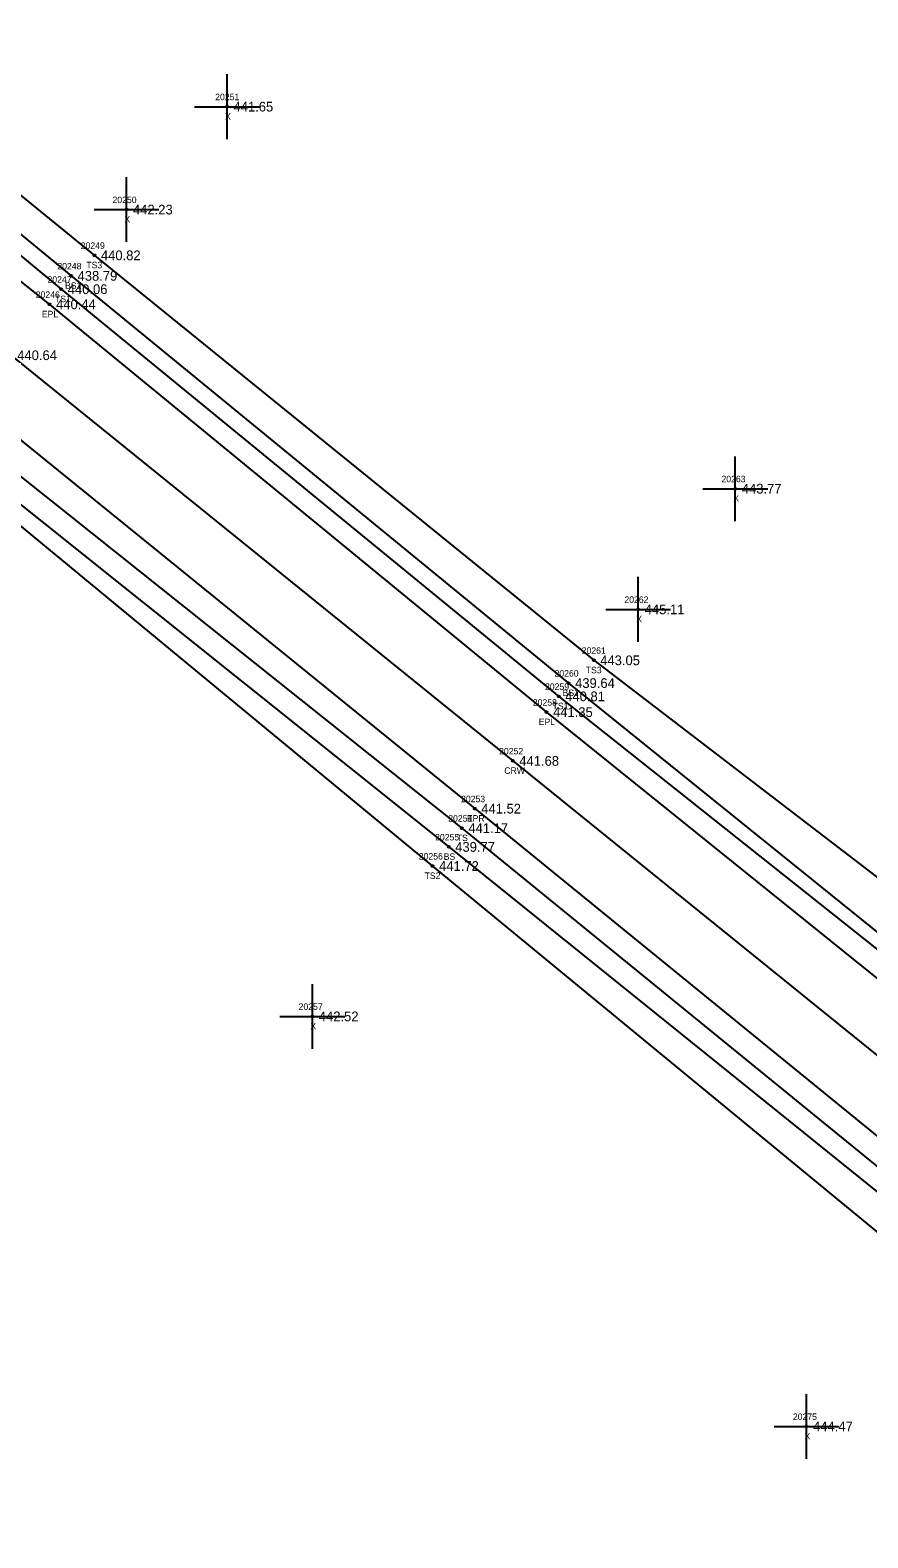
# Model space of a CAD drawing. Extents: x 1613836 to 1615109, y 777151 to 778248.
# Drawn here: x 1614680.1 to 1614809.5, y 777339.3 to 777572.2 of the extents above; entities that cross this region are included whole.
import ezdxf

# ---------------------------------------------------------------- set-up
doc = ezdxf.new("R2010")
doc.units = 0
for name, color, linetype in [('RD_DTM_BkLn1', 7, 'Continuous'), ('RD_DTM_BkLn2', 7, 'Continuous'), ('RD_DTM_BkLn_txCode', 7, 'Continuous'), ('RD_EX_Misc', 7, 'Continuous'), ('RD_EX_Misc_txCode', 7, 'Continuous'), ('RD_EX_Road', 7, 'Continuous'), ('RD_EX_Road_txCode', 7, 'Continuous'), ('RD_EX_TX_Misc_ELEV', 7, 'Continuous'), ('RD_EX_TX_Road_ELEV', 7, 'Continuous'), ('RD_HC_Survey_ELEV', 7, 'Continuous'), ('RD_HC_Survey_txCode', 7, 'Continuous'), ('RD_SMD_Locator', 7, 'Continuous')]:
    doc.layers.add(name, color=color, linetype=linetype)

msp = doc.modelspace()

# ---------------------------------------------------------------- linework, layer by layer
at = {"layer": 'RD_DTM_BkLn1'}
msp.add_lwpolyline([(1614479.01, 777681.63), (1614521.59, 777647.42), (1614599.56, 777584.67), (1614677.14, 777521.99), (1614754.7, 777459.32), (1614832.45, 777396.45), (1614909.52, 777332.99), (1614951.1, 777299.39), (1614987.2, 777270.31), (1615065.15, 777207.54)], dxfattribs=at)
at = {"layer": 'RD_DTM_BkLn2'}
for points in [[(1614480.98, 777699.79), (1614497.59, 777703), (1614522.19, 777696.07), (1614543.87, 777680.98), (1614547.65, 777678.09), (1614587.23, 777635.96), (1614610.74, 777599.44), (1614633.11, 777578.17), (1614686.46, 777534.25), (1614763.32, 777471.34), (1614841.29, 777408.4), (1614909.19, 777352.07)], [(1614487.8, 777694.98), (1614468.11, 777671.48), (1614470.95, 777667.94), (1614510.68, 777634.64), (1614563.11, 777597.11), (1614590.8, 777573.1), (1614668.37, 777511.43), (1614746.83, 777448.93), (1614824, 777386.05), (1614902.11, 777323.38), (1614943.6, 777288.77), (1614978.33, 777258.85), (1615057.35, 777197.32)], [(1614487.8, 777694.98), (1614492.09, 777693.24), (1614539.12, 777670.15), (1614581.25, 777629.02), (1614608.07, 777595.47), (1614631.79, 777576.16), (1614684.94, 777532.19), (1614761.79, 777469.29), (1614840.42, 777406.78), (1614908.46, 777350.38), (1614912.05, 777350.16), (1614911.85, 777355.47)], [(1614459.93, 777668.19), (1614463.78, 777659.09), (1614488.02, 777636.81), (1614504.08, 777625.83), (1614559.77, 777590.67), (1614588.99, 777571.17), (1614666.25, 777508.81), (1614744.8, 777446.03), (1614822.12, 777383.78), (1614899.86, 777320.65), (1614938.98, 777288.55), (1614940.53, 777287.22)], [(1614614.42, 777605.82), (1614635.25, 777582.12), (1614690.07, 777537.42), (1614767.2, 777474.86), (1614846.75, 777413.92), (1614911.85, 777355.47)], [(1614586.97, 777568.57), (1614664.83, 777506.94), (1614742.31, 777443.08), (1614819.3, 777379.66), (1614897.91, 777318.71), (1614936.23, 777288.24)]]:
    msp.add_lwpolyline(points, dxfattribs=at)
at = {"layer": 'RD_EX_Misc'}
for p, q in [((1614710.55, 777555.39), (1614710.55, 777565.39)), ((1614705.55, 777560.39), (1614715.55, 777560.39)), ((1614695.02, 777539.49), (1614695.02, 777549.49)), ((1614690.02, 777544.49), (1614700.02, 777544.49)), ((1614789.07, 777496.37), (1614789.07, 777506.37)), ((1614784.07, 777501.37), (1614794.07, 777501.37)), ((1614774.07, 777477.73), (1614774.07, 777487.73)), ((1614769.07, 777482.73), (1614779.07, 777482.73)), ((1614723.73, 777414.85), (1614723.73, 777424.85)), ((1614718.73, 777419.85), (1614728.73, 777419.85)), ((1614800.08, 777351.5), (1614800.08, 777361.5)), ((1614795.08, 777356.5), (1614805.08, 777356.5))]:
    msp.add_line(p, q, dxfattribs=at)
at = {"layer": 'RD_EX_Road'}
for points in [[(1614484.15, 777687.93), (1614479.01, 777681.63), (1614474.14, 777675.5), (1614516.4, 777641.23), (1614565.54, 777600.82), (1614593.96, 777577.93), (1614671.57, 777514.59), (1614748.82, 777451.94), (1614826.23, 777388.93), (1614903.92, 777325.97), (1614945.38, 777292), (1614981.73, 777262.81), (1615059.73, 777200.12)], [(1614484.15, 777687.93), (1614527.25, 777653.67), (1614604.97, 777591.41), (1614629.13, 777572.93), (1614683.14, 777529.85), (1614759.91, 777466.85), (1614838.21, 777403.78), (1614915.19, 777340.18), (1614934.98, 777324.5), (1615070.79, 777214.66)]]:
    msp.add_lwpolyline(points, dxfattribs=at)
at = {"layer": 'RD_SMD_Locator'}
for centre in [(1614710.55, 777560.39), (1614695.02, 777544.49), (1614690.07, 777537.42), (1614686.46, 777534.25), (1614684.94, 777532.19), (1614683.14, 777529.85), (1614789.07, 777501.37), (1614774.07, 777482.73), (1614767.2, 777474.86), (1614763.32, 777471.34), (1614761.79, 777469.29), (1614759.91, 777466.85), (1614754.7, 777459.32), (1614748.82, 777451.94), (1614746.83, 777448.93), (1614744.8, 777446.03), (1614742.31, 777443.08), (1614723.73, 777419.85), (1614800.08, 777356.5)]:
    msp.add_circle(centre, 0.15, dxfattribs=at)

# ---------------------------------------------------------------- texts
at = {"layer": 'RD_DTM_BkLn_txCode'}
for s, p in [('20249', (1614687.95, 777538.42)), ('20248', (1614684.34, 777535.25)), ('TS3', (1614688.82, 777535.42)), ('20247', (1614682.82, 777533.19)), ('BS1', (1614685.52, 777532.25)), ('TS1', (1614683.98, 777530.19)), ('20261', (1614765.34, 777475.86)), ('20260', (1614761.14, 777472.34)), ('TS3', (1614765.96, 777472.86)), ('20259', (1614759.67, 777470.29)), ('BS1', (1614762.38, 777469.34)), ('TS1', (1614760.83, 777467.29)), ('20254', (1614744.72, 777449.93)), ('20255', (1614742.69, 777447.03)), ('TS', (1614746.04, 777446.93)), ('20256', (1614740.17, 777444.08)), ('BS', (1614744.02, 777444.03)), ('TS2', (1614741.07, 777441.08))]:
    msp.add_text(s, height=1, dxfattribs=at).set_placement(p)
at = {"layer": 'RD_EX_Misc_txCode'}
for s, p in [('20251', (1614708.72, 777561.39)), ('X', (1614710.24, 777558.39)), ('20250', (1614692.86, 777545.49)), ('X', (1614694.7, 777542.49)), ('20263', (1614786.93, 777502.37)), ('X', (1614788.75, 777499.37)), ('20262', (1614771.93, 777483.73)), ('X', (1614773.76, 777480.73)), ('20257', (1614721.61, 777420.85)), ('X', (1614723.42, 777417.85)), ('20275', (1614797.96, 777357.5)), ('X', (1614799.76, 777354.5))]:
    msp.add_text(s, height=1, dxfattribs=at).set_placement(p)
at = {"layer": 'RD_EX_Road_txCode'}
for s, p in [('20246', (1614681, 777530.85)), ('EPL', (1614681.94, 777527.85)), ('20258', (1614757.79, 777467.85)), ('EPL', (1614758.7, 777464.85)), ('20253', (1614746.7, 777452.94)), ('EPR', (1614747.59, 777449.94))]:
    msp.add_text(s, height=1, dxfattribs=at).set_placement(p)
at = {"layer": 'RD_EX_TX_Misc_ELEV'}
for s, p in [('441.65', (1614711.55, 777559.64)), ('442.23', (1614696.02, 777543.74)), ('440.82', (1614691.07, 777536.67)), ('438.79', (1614687.46, 777533.5)), ('440.06', (1614685.94, 777531.44)), ('443.77', (1614790.07, 777500.62)), ('445.11', (1614775.07, 777481.98)), ('443.05', (1614768.2, 777474.11)), ('439.64', (1614764.32, 777470.59)), ('440.81', (1614762.79, 777468.54)), ('441.17', (1614747.83, 777448.18)), ('439.77', (1614745.8, 777445.28)), ('441.72', (1614743.31, 777442.33)), ('442.52', (1614724.73, 777419.1)), ('444.47', (1614801.08, 777355.75))]:
    msp.add_text(s, height=1.5, dxfattribs=at).set_placement(p)
at = {"layer": 'RD_EX_TX_Road_ELEV'}
for s, p in [('440.44', (1614684.14, 777529.1)), ('441.35', (1614760.91, 777466.1)), ('441.52', (1614749.82, 777451.19))]:
    msp.add_text(s, height=1.5, dxfattribs=at).set_placement(p)
at = {"layer": 'RD_HC_Survey_ELEV'}
for s, p in [('440.64', (1614678.14, 777521.24)), ('441.68', (1614755.7, 777458.57))]:
    msp.add_text(s, height=1.5, dxfattribs=at).set_placement(p)
at = {"layer": 'RD_HC_Survey_txCode'}
for s, p in [('20252', (1614752.58, 777460.32)), ('CRW', (1614753.38, 777457.32))]:
    msp.add_text(s, height=1, dxfattribs=at).set_placement(p)

doc.saveas('drawing.dxf')
